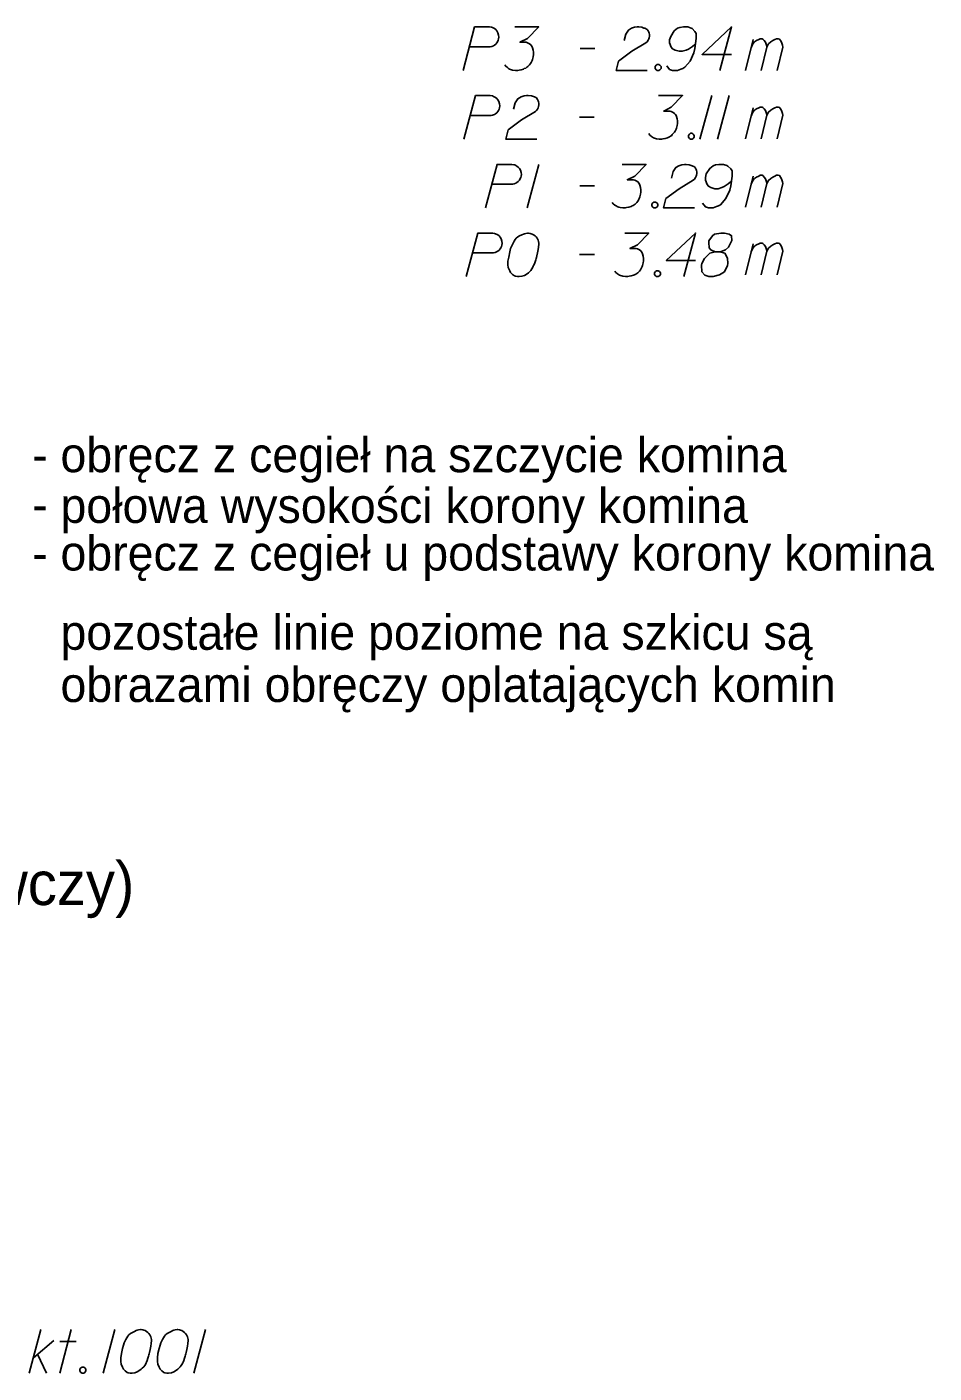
# Model space of a CAD drawing. Extents: x 138 to 264, y -75 to 121.
# Drawn here: x 178.09 to 185.4, y 55.54 to 66.37 of the extents above; entities that cross this region are included whole.
import ezdxf

# ---------------------------------------------------------------- set-up
doc = ezdxf.new("R2010")
doc.units = 0
doc.layers.add('Standard', color=7, linetype='Continuous')

msp = doc.modelspace()

# ---------------------------------------------------------------- linework, layer by layer
at = {"layer": 'Standard'}
for points in [[(181.604, 66.021), (181.697, 66.371), (181.816, 66.371), (181.832, 66.368), (181.841, 66.365), (181.857, 66.357), (181.868, 66.349), (181.876, 66.338), (181.885, 66.324), (181.89, 66.305), (181.893, 66.288), (181.89, 66.274), (181.887, 66.263), (181.882, 66.252), (181.876, 66.244), (181.868, 66.233), (181.857, 66.225), (181.849, 66.219), (181.835, 66.214), (181.821, 66.211), (181.656, 66.211)], [(182.02, 66.371), (182.213, 66.371), (182.122, 66.277), (182.061, 66.247), (182.111, 66.247), (182.122, 66.244), (182.127, 66.241), (182.133, 66.238), (182.138, 66.236), (182.149, 66.227), (182.155, 66.219), (182.16, 66.211), (182.163, 66.203), (182.169, 66.183), (182.171, 66.167), (182.171, 66.159), (182.171, 66.148), (182.169, 66.131), (182.166, 66.12), (182.163, 66.109), (182.16, 66.101), (182.158, 66.095), (182.155, 66.09), (182.152, 66.084), (182.147, 66.076), (182.138, 66.065), (182.13, 66.057), (182.124, 66.051), (182.116, 66.046), (182.108, 66.04), (182.097, 66.035), (182.091, 66.032), (182.072, 66.026), (182.056, 66.024), (182.045, 66.021), (182.025, 66.021), (182.003, 66.024), (181.995, 66.026), (181.987, 66.029), (181.978, 66.032), (181.97, 66.037), (181.962, 66.043), (181.948, 66.054), (181.94, 66.065)], [(182.9, 66.261), (182.914, 66.313), (182.936, 66.346), (182.961, 66.36), (182.985, 66.368), (183.005, 66.371), (183.018, 66.371), (183.043, 66.368), (183.06, 66.362), (183.068, 66.36), (183.085, 66.351), (183.093, 66.34), (183.098, 66.329), (183.101, 66.321), (183.104, 66.31), (183.104, 66.296), (183.101, 66.283), (183.098, 66.274), (183.093, 66.263), (183.085, 66.252), (183.076, 66.244), (182.963, 66.175), (182.856, 66.095), (182.837, 66.021), (183.087, 66.021)], [(183.244, 66.059), (183.266, 66.029), (183.291, 66.021), (183.33, 66.021), (183.357, 66.032), (183.374, 66.037), (183.388, 66.046), (183.432, 66.095), (183.462, 66.161), (183.47, 66.197), (183.481, 66.277), (183.481, 66.318), (183.47, 66.335), (183.448, 66.357), (183.44, 66.362), (183.413, 66.371), (183.377, 66.371), (183.349, 66.365), (183.33, 66.36), (183.302, 66.338), (183.275, 66.294), (183.266, 66.266), (183.266, 66.244), (183.28, 66.208), (183.291, 66.194), (183.311, 66.183), (183.344, 66.175), (183.368, 66.175), (183.399, 66.183), (183.418, 66.192), (183.451, 66.214), (183.468, 66.227), (183.476, 66.236)], [(183.765, 66.15), (183.528, 66.15), (183.765, 66.371), (183.672, 66.021)], [(182.546, 66.197), (182.665, 66.197)], [(183.876, 66.019), (183.939, 66.269)], [(183.923, 66.203), (183.937, 66.234), (183.95, 66.25), (183.967, 66.261), (183.984, 66.269), (183.995, 66.275), (184.011, 66.275), (184.017, 66.272), (184.028, 66.261), (184.039, 66.247), (184.047, 66.223), (184.05, 66.209), (184.063, 66.234), (184.08, 66.25), (184.096, 66.261), (184.113, 66.269), (184.127, 66.275), (184.141, 66.275), (184.152, 66.272), (184.16, 66.261), (184.168, 66.247), (184.176, 66.223), (184.179, 66.209), (184.132, 66.019)], [(184.003, 66.019), (184.05, 66.209)], [(183.167, 66.068), (183.181, 66.068), (183.189, 66.062), (183.198, 66.051), (183.198, 66.037), (183.189, 66.026), (183.181, 66.021), (183.167, 66.021), (183.159, 66.026), (183.151, 66.037), (183.151, 66.051), (183.159, 66.062), (183.167, 66.068)], [(181.611, 65.468), (181.705, 65.818), (181.823, 65.818), (181.84, 65.815), (181.848, 65.812), (181.864, 65.804), (181.875, 65.796), (181.884, 65.785), (181.892, 65.771), (181.897, 65.752), (181.9, 65.735), (181.897, 65.721), (181.895, 65.71), (181.889, 65.699), (181.884, 65.691), (181.875, 65.68), (181.864, 65.672), (181.856, 65.666), (181.842, 65.661), (181.829, 65.658), (181.663, 65.658)], [(182.01, 65.708), (182.024, 65.76), (182.046, 65.793), (182.071, 65.807), (182.096, 65.815), (182.115, 65.818), (182.129, 65.818), (182.154, 65.815), (182.17, 65.81), (182.179, 65.807), (182.195, 65.799), (182.203, 65.788), (182.209, 65.777), (182.212, 65.768), (182.214, 65.757), (182.214, 65.743), (182.212, 65.73), (182.209, 65.721), (182.203, 65.71), (182.195, 65.699), (182.187, 65.691), (182.074, 65.622), (181.966, 65.542), (181.947, 65.468), (182.198, 65.468)], [(183.178, 65.818), (183.371, 65.818), (183.28, 65.724), (183.219, 65.694), (183.269, 65.694), (183.28, 65.691), (183.285, 65.688), (183.291, 65.686), (183.296, 65.683), (183.307, 65.675), (183.313, 65.666), (183.318, 65.658), (183.321, 65.65), (183.327, 65.631), (183.329, 65.614), (183.329, 65.606), (183.329, 65.595), (183.327, 65.578), (183.324, 65.567), (183.321, 65.556), (183.318, 65.548), (183.316, 65.542), (183.313, 65.537), (183.31, 65.531), (183.305, 65.523), (183.296, 65.512), (183.288, 65.504), (183.283, 65.498), (183.274, 65.493), (183.266, 65.487), (183.255, 65.482), (183.249, 65.479), (183.23, 65.473), (183.214, 65.471), (183.203, 65.468), (183.183, 65.468), (183.161, 65.471), (183.153, 65.473), (183.145, 65.476), (183.136, 65.479), (183.128, 65.484), (183.12, 65.49), (183.106, 65.501), (183.098, 65.512)], [(183.605, 65.818), (183.511, 65.468)], [(183.745, 65.818), (183.652, 65.468)], [(182.541, 65.644), (182.66, 65.644)], [(183.876, 65.47), (183.939, 65.72)], [(183.923, 65.654), (183.937, 65.685), (183.95, 65.701), (183.967, 65.712), (183.984, 65.72), (183.995, 65.726), (184.011, 65.726), (184.017, 65.723), (184.028, 65.712), (184.039, 65.698), (184.047, 65.674), (184.05, 65.66), (184.063, 65.685), (184.08, 65.701), (184.096, 65.712), (184.113, 65.72), (184.127, 65.726), (184.141, 65.726), (184.152, 65.723), (184.16, 65.712), (184.168, 65.698), (184.176, 65.674), (184.179, 65.66), (184.132, 65.47)], [(184.003, 65.47), (184.05, 65.66)], [(183.434, 65.515), (183.448, 65.515), (183.456, 65.509), (183.464, 65.498), (183.464, 65.484), (183.456, 65.473), (183.448, 65.468), (183.434, 65.468), (183.426, 65.473), (183.418, 65.484), (183.418, 65.498), (183.426, 65.509), (183.434, 65.515)], [(181.784, 64.915), (181.878, 65.265), (181.996, 65.265), (182.013, 65.262), (182.021, 65.26), (182.037, 65.251), (182.048, 65.243), (182.057, 65.232), (182.065, 65.218), (182.071, 65.199), (182.073, 65.182), (182.071, 65.169), (182.068, 65.158), (182.062, 65.147), (182.057, 65.138), (182.048, 65.127), (182.037, 65.119), (182.029, 65.113), (182.015, 65.108), (182.002, 65.105), (181.836, 65.105)], [(182.214, 65.265), (182.12, 64.915)], [(182.884, 65.265), (183.077, 65.265), (182.986, 65.171), (182.926, 65.141), (182.975, 65.141), (182.986, 65.138), (182.992, 65.135), (182.997, 65.133), (183.003, 65.13), (183.014, 65.122), (183.019, 65.113), (183.025, 65.105), (183.028, 65.097), (183.033, 65.078), (183.036, 65.061), (183.036, 65.053), (183.036, 65.042), (183.033, 65.025), (183.03, 65.014), (183.028, 65.003), (183.025, 64.995), (183.022, 64.989), (183.019, 64.984), (183.017, 64.978), (183.011, 64.97), (183.003, 64.959), (182.994, 64.951), (182.989, 64.945), (182.981, 64.94), (182.972, 64.934), (182.961, 64.929), (182.956, 64.926), (182.937, 64.921), (182.92, 64.918), (182.909, 64.915), (182.89, 64.915), (182.868, 64.918), (182.859, 64.921), (182.851, 64.923), (182.843, 64.926), (182.835, 64.932), (182.826, 64.937), (182.813, 64.948), (182.804, 64.959)], [(183.281, 65.155), (183.295, 65.207), (183.317, 65.24), (183.342, 65.254), (183.366, 65.262), (183.386, 65.265), (183.4, 65.265), (183.424, 65.262), (183.441, 65.257), (183.449, 65.254), (183.466, 65.246), (183.474, 65.235), (183.479, 65.224), (183.482, 65.215), (183.485, 65.204), (183.485, 65.191), (183.482, 65.177), (183.479, 65.169), (183.474, 65.158), (183.466, 65.147), (183.457, 65.138), (183.344, 65.069), (183.237, 64.989), (183.218, 64.915), (183.468, 64.915)], [(183.532, 64.954), (183.554, 64.923), (183.579, 64.915), (183.617, 64.915), (183.645, 64.926), (183.661, 64.932), (183.675, 64.94), (183.719, 64.989), (183.75, 65.056), (183.758, 65.091), (183.769, 65.171), (183.769, 65.213), (183.758, 65.229), (183.736, 65.251), (183.727, 65.257), (183.7, 65.265), (183.664, 65.265), (183.637, 65.26), (183.617, 65.254), (183.59, 65.232), (183.562, 65.188), (183.554, 65.16), (183.554, 65.138), (183.568, 65.102), (183.579, 65.089), (183.598, 65.078), (183.631, 65.069), (183.656, 65.069), (183.686, 65.078), (183.705, 65.086), (183.739, 65.108), (183.755, 65.122), (183.763, 65.13)], [(183.876, 64.921), (183.939, 65.171)], [(183.923, 65.105), (183.937, 65.136), (183.95, 65.152), (183.967, 65.163), (183.984, 65.171), (183.995, 65.177), (184.011, 65.177), (184.017, 65.174), (184.028, 65.163), (184.039, 65.149), (184.047, 65.125), (184.05, 65.111), (184.063, 65.136), (184.08, 65.152), (184.096, 65.163), (184.113, 65.171), (184.127, 65.177), (184.141, 65.177), (184.152, 65.174), (184.16, 65.163), (184.168, 65.149), (184.176, 65.125), (184.179, 65.111), (184.132, 64.921)], [(184.003, 64.921), (184.05, 65.111)], [(182.545, 65.091), (182.663, 65.091)], [(183.14, 64.962), (183.154, 64.962), (183.163, 64.956), (183.171, 64.945), (183.171, 64.932), (183.163, 64.921), (183.154, 64.915), (183.14, 64.915), (183.132, 64.921), (183.124, 64.932), (183.124, 64.945), (183.132, 64.956), (183.14, 64.962)], [(181.629, 64.362), (181.723, 64.712), (181.841, 64.712), (181.858, 64.709), (181.866, 64.707), (181.883, 64.698), (181.894, 64.69), (181.902, 64.679), (181.91, 64.665), (181.916, 64.646), (181.919, 64.629), (181.916, 64.616), (181.913, 64.605), (181.908, 64.594), (181.902, 64.585), (181.894, 64.574), (181.883, 64.566), (181.874, 64.561), (181.861, 64.555), (181.847, 64.552), (181.682, 64.552)], [(182.131, 64.712), (182.125, 64.712), (182.109, 64.709), (182.098, 64.707), (182.089, 64.704), (182.076, 64.698), (182.059, 64.69), (182.045, 64.682), (182.032, 64.671), (182.023, 64.66), (182.015, 64.646), (182.007, 64.632), (181.998, 64.616), (181.993, 64.605), (181.987, 64.588), (181.979, 64.561), (181.971, 64.519), (181.965, 64.486), (181.965, 64.456), (181.968, 64.434), (181.979, 64.409), (181.987, 64.395), (182.001, 64.379), (182.018, 64.368), (182.026, 64.365), (182.043, 64.362), (182.056, 64.362), (182.078, 64.365), (182.098, 64.37), (182.111, 64.379), (182.131, 64.393), (182.139, 64.401), (182.15, 64.412), (182.158, 64.423), (182.164, 64.431), (182.169, 64.445), (182.172, 64.45), (182.178, 64.464), (182.183, 64.481), (182.189, 64.497), (182.191, 64.508), (182.194, 64.516), (182.197, 64.528), (182.202, 64.552), (182.205, 64.566), (182.208, 64.58), (182.211, 64.599), (182.213, 64.624), (182.213, 64.632), (182.211, 64.643), (182.208, 64.654), (182.2, 64.671), (182.191, 64.682), (182.183, 64.69), (182.172, 64.698), (182.161, 64.704), (182.153, 64.707), (182.145, 64.709), (182.131, 64.712)], [(182.905, 64.712), (183.098, 64.712), (183.007, 64.618), (182.947, 64.588), (182.996, 64.588), (183.007, 64.585), (183.013, 64.583), (183.018, 64.58), (183.024, 64.577), (183.035, 64.569), (183.04, 64.561), (183.046, 64.552), (183.049, 64.544), (183.054, 64.525), (183.057, 64.508), (183.057, 64.5), (183.057, 64.489), (183.054, 64.472), (183.051, 64.461), (183.049, 64.45), (183.046, 64.442), (183.043, 64.437), (183.04, 64.431), (183.038, 64.426), (183.032, 64.417), (183.024, 64.406), (183.016, 64.398), (183.01, 64.393), (183.002, 64.387), (182.994, 64.381), (182.983, 64.376), (182.977, 64.373), (182.958, 64.368), (182.941, 64.365), (182.93, 64.362), (182.911, 64.362), (182.889, 64.365), (182.881, 64.368), (182.872, 64.37), (182.864, 64.373), (182.856, 64.379), (182.848, 64.384), (182.834, 64.395), (182.825, 64.406)], [(183.476, 64.492), (183.239, 64.492), (183.476, 64.712), (183.382, 64.362)], [(183.633, 64.561), (183.671, 64.561), (183.682, 64.563), (183.716, 64.577), (183.74, 64.599), (183.768, 64.652), (183.765, 64.69), (183.746, 64.704), (183.707, 64.712), (183.68, 64.712), (183.627, 64.704), (183.611, 64.69), (183.583, 64.649), (183.581, 64.635), (183.586, 64.594), (183.597, 64.577), (183.633, 64.561), (183.589, 64.55), (183.547, 64.508), (183.525, 64.467), (183.523, 64.453), (183.525, 64.401), (183.55, 64.373), (183.583, 64.362), (183.616, 64.362), (183.669, 64.376), (183.707, 64.401), (183.732, 64.45), (183.735, 64.467), (183.732, 64.511), (183.71, 64.55), (183.671, 64.561)], [(183.876, 64.375), (183.939, 64.626)], [(183.923, 64.56), (183.937, 64.59), (183.95, 64.607), (183.967, 64.618), (183.984, 64.626), (183.995, 64.632), (184.011, 64.632), (184.017, 64.629), (184.028, 64.618), (184.039, 64.604), (184.047, 64.579), (184.05, 64.566), (184.063, 64.59), (184.08, 64.607), (184.096, 64.618), (184.113, 64.626), (184.127, 64.632), (184.141, 64.632), (184.152, 64.629), (184.16, 64.618), (184.168, 64.604), (184.176, 64.579), (184.179, 64.566), (184.132, 64.375)], [(184.003, 64.375), (184.05, 64.566)], [(182.542, 64.539), (182.661, 64.539)], [(183.162, 64.409), (183.175, 64.409), (183.184, 64.404), (183.192, 64.393), (183.192, 64.379), (183.184, 64.368), (183.175, 64.362), (183.162, 64.362), (183.153, 64.368), (183.145, 64.379), (183.145, 64.393), (183.153, 64.404), (183.162, 64.409)], [(178.112, 55.539), (178.206, 55.889)], [(178.145, 55.663), (178.311, 55.801)], [(178.358, 55.539), (178.449, 55.889)], [(178.358, 55.793), (178.49, 55.793)], [(178.801, 55.889), (178.708, 55.539)], [(179.013, 55.889), (179.008, 55.889), (178.991, 55.886), (178.98, 55.884), (178.972, 55.881), (178.958, 55.875), (178.942, 55.867), (178.928, 55.859), (178.914, 55.848), (178.906, 55.837), (178.898, 55.823), (178.889, 55.809), (178.881, 55.793), (178.876, 55.782), (178.87, 55.765), (178.862, 55.738), (178.854, 55.696), (178.848, 55.663), (178.848, 55.633), (178.851, 55.611), (178.862, 55.586), (178.87, 55.572), (178.884, 55.556), (178.9, 55.545), (178.909, 55.542), (178.925, 55.539), (178.939, 55.539), (178.961, 55.542), (178.98, 55.548), (178.994, 55.556), (179.013, 55.57), (179.022, 55.578), (179.033, 55.589), (179.041, 55.6), (179.047, 55.608), (179.052, 55.622), (179.055, 55.627), (179.06, 55.641), (179.066, 55.658), (179.071, 55.674), (179.074, 55.685), (179.077, 55.694), (179.08, 55.705), (179.085, 55.729), (179.088, 55.743), (179.091, 55.757), (179.093, 55.776), (179.096, 55.801), (179.096, 55.809), (179.093, 55.82), (179.091, 55.831), (179.082, 55.848), (179.074, 55.859), (179.066, 55.867), (179.055, 55.875), (179.044, 55.881), (179.035, 55.884), (179.027, 55.886), (179.013, 55.889)], [(179.308, 55.889), (179.303, 55.889), (179.286, 55.886), (179.275, 55.884), (179.267, 55.881), (179.253, 55.875), (179.237, 55.867), (179.223, 55.859), (179.209, 55.848), (179.201, 55.837), (179.193, 55.823), (179.184, 55.809), (179.176, 55.793), (179.17, 55.782), (179.165, 55.765), (179.157, 55.738), (179.148, 55.696), (179.143, 55.663), (179.143, 55.633), (179.146, 55.611), (179.157, 55.586), (179.165, 55.572), (179.179, 55.556), (179.195, 55.545), (179.204, 55.542), (179.22, 55.539), (179.234, 55.539), (179.256, 55.542), (179.275, 55.548), (179.289, 55.556), (179.308, 55.57), (179.317, 55.578), (179.328, 55.589), (179.336, 55.6), (179.341, 55.608), (179.347, 55.622), (179.35, 55.627), (179.355, 55.641), (179.361, 55.658), (179.366, 55.674), (179.369, 55.685), (179.372, 55.694), (179.374, 55.705), (179.38, 55.729), (179.383, 55.743), (179.385, 55.757), (179.388, 55.776), (179.391, 55.801), (179.391, 55.809), (179.388, 55.82), (179.385, 55.831), (179.377, 55.848), (179.369, 55.859), (179.361, 55.867), (179.35, 55.875), (179.339, 55.881), (179.33, 55.884), (179.322, 55.886), (179.308, 55.889)], [(179.531, 55.889), (179.438, 55.539)], [(178.179, 55.691), (178.25, 55.539)], [(178.537, 55.586), (178.551, 55.586), (178.559, 55.581), (178.567, 55.57), (178.567, 55.556), (178.559, 55.545), (178.551, 55.539), (178.537, 55.539), (178.528, 55.545), (178.52, 55.556), (178.52, 55.57), (178.528, 55.581), (178.537, 55.586)]]:
    msp.add_lwpolyline(points, dxfattribs=at)

# ---------------------------------------------------------------- texts
for s, height, p in [('obręcz z cegieł na szczycie komina', 0.27991, (178.363, 62.788)), ('-', 0.28, (178.136, 62.788)), ('połowa wysokości korony komina', 0.27991, (178.363, 62.38)), ('-', 0.28, (178.136, 62.389)), ('obręcz z cegieł u podstawy korony komina', 0.27991, (178.363, 61.997)), ('-', 0.28, (178.137, 61.997)), ('pozostałe linie poziome na szkicu są', 0.27991, (178.363, 61.359)), ('obrazami obręczy oplatających komin', 0.27991, (178.363, 60.939)), ('(poziom porównawczy)', 0.35, (174.172, 59.305))]:
    msp.add_text(s, height=height, dxfattribs=at).set_placement(p)

doc.saveas('drawing.dxf')
